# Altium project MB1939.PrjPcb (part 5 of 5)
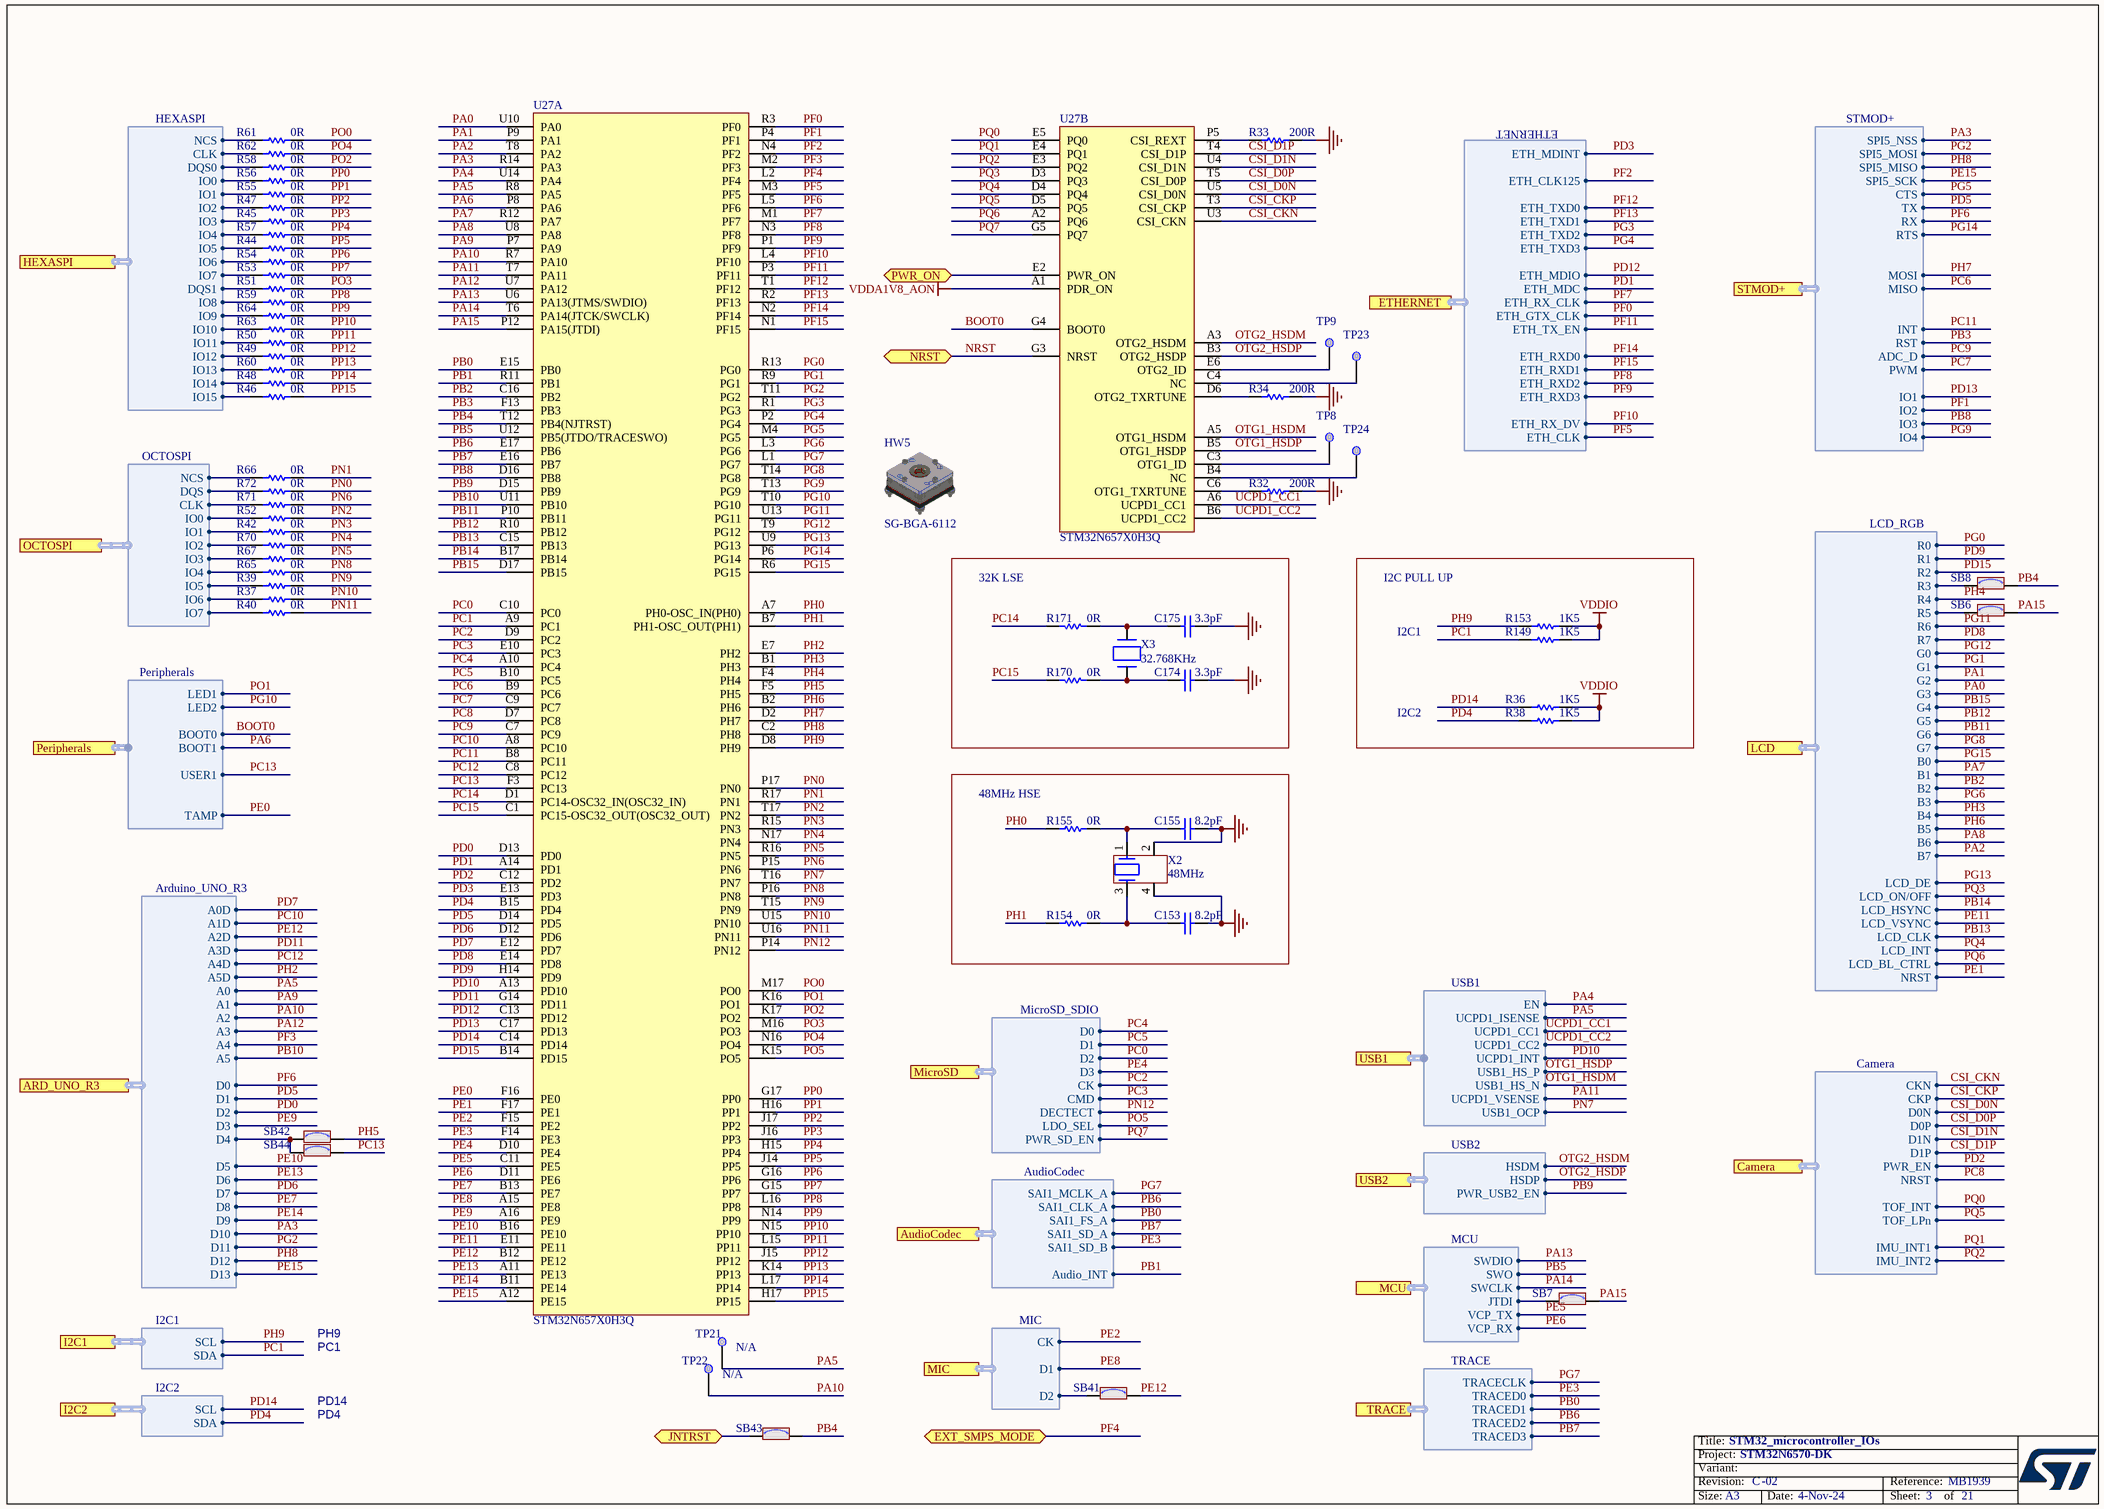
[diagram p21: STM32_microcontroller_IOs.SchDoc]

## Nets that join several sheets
5V: Arduino_UNO_R3_SMD (CN8.5), LCD (R43.1), STLINK_V3EC (D2.1 R113.2), STMOD+ (CN4.6 CN4.15), USB2 (C190.2 U47.5), USB1_DRP (SB48.1), Camera (C199.2 U54.3), Power (21 pins)
5V_STLK: STLINK_V3EC (6 pins), Power (JP2.1)
5V_USB_SNK: USB1_DRP (SB46.1), Power (JP2.3)
5V_VIN: Arduino_UNO_R3_SMD (R111.2), Power (C134.2 JP2.5 U21.2 U21.4)
GND: Arduino_UNO_R3_SMD (15 pins), Ethernet (38 pins), External_Debug_Interface (13 pins), HexaSPI_PSRAM (6 pins), LCD (13 pins), Peripherals (12 pins), MEMs_microphone (7 pins), OctoSPI_Flash (9 pins), SDcard (18 pins), STLINK_V3EC (105 pins), STMOD+ (CN4.5 CN4.16), USB2 (11 pins), Mechanical (H1.1 H2.1 H7.1 H8.1), STM32_microcontroller_power (76 pins), Audio_Codec (21 pins), USB1_DRP (26 pins), Camera (27 pins), Power (53 pins), STM32_microcontroller_IOs (9 pins)
VDD1V8: STM32_microcontroller_power (L4.1 L8.1), Power (R21.2)
VDD3V3: Arduino_UNO_R3_SMD (CN8.2 CN8.4 R131.2), Ethernet (SB3.1), LCD (C81.1 CN3.50), Peripherals (LD1.1 LD2.1), MEMs_microphone (SB19.1), SDcard (R145.1), USB2 (LD8.1), STM32_microcontroller_power (R159.1), Audio_Codec (SB38.1), USB1_DRP (LD10.1 R212.1 U46.2), Camera (SB45.1), Power (5 pins)
VDDA1V8: Arduino_UNO_R3_SMD (U6.8 U7.8 U8.8), HexaSPI_PSRAM (SB35.1), OctoSPI_Flash (SB36.1), SDcard (R143.2 U32.1), STM32_microcontroller_power (22 pins), Audio_Codec (SB37.1), Power (R179.2 TP17.1)
VDDA1V8_AON: STM32_microcontroller_power (C36.2 R148.1), Power (R163.2 TP15.1), STM32_microcontroller_IOs (U27.A1)
VDDCORE: STM32_microcontroller_power (21 pins), Power (R30.2 TP10.1)
VDDIO: External_Debug_Interface (CN1.1 CN10.1 R5.2), Peripherals (6 pins), SDcard (C152.2 U32.5), STLINK_V3EC (LNK3.1), STM32_microcontroller_power (17 pins), Power (R78.2 TP13.1), STM32_microcontroller_IOs (R36.1 R38.1 R149.1 R153.1)
VDDIO_SD: SDcard (6 pins), STM32_microcontroller_power (C59.2 C64.2 U27.E9 U27.F9)
VIN: Arduino_UNO_R3_SMD (CN8.8), Power (C131.2 U21.3)
VREFP: Arduino_UNO_R3_SMD (C140.1 R137.2), STM32_microcontroller_power (C38.2 C39.2 R27.2 U27.U2)
ARD_A0: Arduino_UNO_R3_SMD (SB49.2), USB1_DRP (SB47.1), STM32_microcontroller_IOs (TP21.1 U27.R8)
ARD_A0D: Arduino_UNO_R3_SMD (SB23.1), STM32_microcontroller_IOs (U27.E12)
ARD_A1: Arduino_UNO_R3_SMD (U8.6 U8.7), STM32_microcontroller_IOs (U27.P7)
ARD_A1D: Arduino_UNO_R3_SMD (SB22.1), STM32_microcontroller_IOs (U27.A8)
ARD_A2: Arduino_UNO_R3_SMD (SB51.2), STM32_microcontroller_IOs (TP22.1 U27.R7)
ARD_A2D: Arduino_UNO_R3_SMD (SB21.1), STM32_microcontroller_IOs (SB41.2 U27.B12)
ARD_A3: Arduino_UNO_R3_SMD (U7.6 U7.7), STM32_microcontroller_IOs (U27.U7)
ARD_A3D: Arduino_UNO_R3_SMD (SB20.1), STM32_microcontroller_IOs (U27.G14)
ARD_A4: Arduino_UNO_R3_SMD (TP5.1 U6.1 U6.2), STM32_microcontroller_IOs (U27.M2)
ARD_A4D: Arduino_UNO_R3_SMD (SB31.1), STM32_microcontroller_IOs (U27.C8)
ARD_A5: Arduino_UNO_R3_SMD (U6.6 U6.7), STM32_microcontroller_IOs (U27.U11)
ARD_A5D: Arduino_UNO_R3_SMD (SB33.1), STM32_microcontroller_IOs (U27.E7)
ARD_D0: Arduino_UNO_R3_SMD (CN11.1), STMOD+ (SB14.1), STM32_microcontroller_IOs (U27.L5)
ARD_D1: Arduino_UNO_R3_SMD (CN11.2), STMOD+ (SB12.1), STM32_microcontroller_IOs (U27.D14)
ARD_D2: Arduino_UNO_R3_SMD (CN11.3), STM32_microcontroller_IOs (U27.D13)
ARD_D3: Arduino_UNO_R3_SMD (CN11.4), STM32_microcontroller_IOs (U27.A16)
ARD_D4: Arduino_UNO_R3_SMD (CN11.5), STM32_microcontroller_IOs (SB42.1 SB44.1)
ARD_D5: Arduino_UNO_R3_SMD (CN11.6), STM32_microcontroller_IOs (U27.B16)
ARD_D6: Arduino_UNO_R3_SMD (CN11.7), STM32_microcontroller_IOs (U27.A11)
ARD_D7: Arduino_UNO_R3_SMD (CN11.8), STM32_microcontroller_IOs (U27.D12)
ARD_D8: Arduino_UNO_R3_SMD (CN12.1), STM32_microcontroller_IOs (U27.B13)
ARD_D9: Arduino_UNO_R3_SMD (CN12.2), STM32_microcontroller_IOs (U27.B11)
ARD_D10: Arduino_UNO_R3_SMD (CN12.3), STMOD+ (SB11.1), STM32_microcontroller_IOs (U27.R14)
ARD_D11: Arduino_UNO_R3_SMD (CN12.4), STMOD+ (SB13.1), STM32_microcontroller_IOs (U27.T11)
ARD_D12: Arduino_UNO_R3_SMD (CN12.5), STMOD+ (SB15.1), STM32_microcontroller_IOs (U27.C2)
ARD_D13: Arduino_UNO_R3_SMD (CN12.6 SB25.1), STMOD+ (SB18.1), STM32_microcontroller_IOs (U27.A12)
ARD_D14: Arduino_UNO_R3_SMD (CN12.9 SB32.1), STMOD+ (CN4.10), Camera (CN14.21 U41.1), STM32_microcontroller_IOs (R149.2 U27.A9)
ARD_D15: Arduino_UNO_R3_SMD (CN12.10 SB34.1), STMOD+ (CN4.7), Camera (CN14.20 U40.1), STM32_microcontroller_IOs (R153.2 U27.D8)
AUDIO_INT: Audio_Codec (R147.2), STM32_microcontroller_IOs (U27.R11)
BOOT0: Peripherals (R103.2), STM32_microcontroller_IOs (U27.G4)
BOOT1: Peripherals (R102.2), STM32_microcontroller_IOs (U27.P8)
CK: MEMs_microphone (CN5.4 R104.2), STM32_microcontroller_IOs (U27.F15)
CSI_CKN: Camera (U31.5), STM32_microcontroller_IOs (U27.U3)
CSI_CKP: Camera (U31.6), STM32_microcontroller_IOs (U27.T3)
CSI_D0_N: Camera (U29.5), STM32_microcontroller_IOs (U27.U5)
CSI_D0_P: Camera (U29.6), STM32_microcontroller_IOs (U27.T5)
CSI_D1_N: Camera (U30.5), STM32_microcontroller_IOs (U27.U4)
CSI_D1_P: Camera (U30.6), STM32_microcontroller_IOs (U27.T4)
D1: MEMs_microphone (TP18.1 U14.4), STM32_microcontroller_IOs (U27.A15)
D2: MEMs_microphone (CN5.5), STM32_microcontroller_IOs (SB41.1)
EN_MODULE: Camera (CN14.18 R222.2 U39.1), STM32_microcontroller_IOs (U27.C12)
ETH_CLK: Ethernet (R203.2), STM32_microcontroller_IOs (U27.M3)
ETH_CLK125: Ethernet (R196.1), STM32_microcontroller_IOs (U27.N4)
ETH_GTX_CLK: Ethernet (R160.1), STM32_microcontroller_IOs (U27.R3)
ETH_MDC: Ethernet (R204.1 U44.13), STM32_microcontroller_IOs (U27.A14)
ETH_MDINT: Ethernet (R186.1 U44.31), STM32_microcontroller_IOs (U27.E13)
ETH_MDIO: Ethernet (R200.1 U44.14), STM32_microcontroller_IOs (U27.C13)
ETH_RX_CLK: Ethernet (R13.2 R176.1 R180.1), STM32_microcontroller_IOs (U27.M1)
ETH_RX_DV: Ethernet (R14.2 R177.1 R181.1), STM32_microcontroller_IOs (U27.L4)
ETH_RXD0: Ethernet (R15.2 R174.1 R182.1), STM32_microcontroller_IOs (U27.N2)
ETH_RXD1: Ethernet (R16.2 R178.1 R183.1), STM32_microcontroller_IOs (U27.N1)
ETH_RXD2: Ethernet (R17.2 R184.1), STM32_microcontroller_IOs (U27.N3)
ETH_RXD3: Ethernet (R18.2 R175.1 R185.1), STM32_microcontroller_IOs (U27.P1)
ETH_TX_EN: Ethernet (R161.1), STM32_microcontroller_IOs (U27.P3)
ETH_TXD0: Ethernet (R162.1), STM32_microcontroller_IOs (U27.T1)
ETH_TXD1: Ethernet (R166.1), STM32_microcontroller_IOs (U27.R2)
ETH_TXD2: Ethernet (R169.1), STM32_microcontroller_IOs (U27.R1)
ETH_TXD3: Ethernet (R172.1), STM32_microcontroller_IOs (U27.P2)
HEXASPI_CLK: HexaSPI_PSRAM (U26.B2), STM32_microcontroller_IOs (R62.1)
HEXASPI_DQS0: HexaSPI_PSRAM (U26.C3), STM32_microcontroller_IOs (R58.1)
HEXASPI_DQS1: HexaSPI_PSRAM (U26.B3), STM32_microcontroller_IOs (R51.1)
HEXASPI_IO0: HexaSPI_PSRAM (U26.D3), STM32_microcontroller_IOs (R56.1)
HEXASPI_IO1: HexaSPI_PSRAM (U26.D2), STM32_microcontroller_IOs (R55.1)
HEXASPI_IO2: HexaSPI_PSRAM (U26.C4), STM32_microcontroller_IOs (R47.1)
HEXASPI_IO3: HexaSPI_PSRAM (U26.D4), STM32_microcontroller_IOs (R45.1)
HEXASPI_IO4: HexaSPI_PSRAM (U26.D5), STM32_microcontroller_IOs (R57.1)
HEXASPI_IO5: HexaSPI_PSRAM (U26.E3), STM32_microcontroller_IOs (R44.1)
HEXASPI_IO6: HexaSPI_PSRAM (U26.E2), STM32_microcontroller_IOs (R54.1)
HEXASPI_IO7: HexaSPI_PSRAM (U26.E1), STM32_microcontroller_IOs (R53.1)
HEXASPI_IO8: HexaSPI_PSRAM (U26.C2), STM32_microcontroller_IOs (R59.1)
HEXASPI_IO9: HexaSPI_PSRAM (U26.B1), STM32_microcontroller_IOs (R64.1)
HEXASPI_IO10: HexaSPI_PSRAM (U26.A2), STM32_microcontroller_IOs (R63.1)
HEXASPI_IO11: HexaSPI_PSRAM (U26.A4), STM32_microcontroller_IOs (R50.1)
HEXASPI_IO12: HexaSPI_PSRAM (U26.A5), STM32_microcontroller_IOs (R49.1)
HEXASPI_IO13: HexaSPI_PSRAM (U26.B4), STM32_microcontroller_IOs (R60.1)
HEXASPI_IO14: HexaSPI_PSRAM (U26.B5), STM32_microcontroller_IOs (R48.1)
HEXASPI_IO15: HexaSPI_PSRAM (U26.C5), STM32_microcontroller_IOs (R46.1)
HEXASPI_NCS: HexaSPI_PSRAM (R138.1 U26.A3), STM32_microcontroller_IOs (R61.1)
I2C2_SCL: LCD (R68.2), Audio_Codec (R226.2), USB1_DRP (R206.1), STM32_microcontroller_IOs (R36.2 U27.C14)
I2C2_SDA: LCD (R69.2), Audio_Codec (R227.2), USB1_DRP (R202.1), STM32_microcontroller_IOs (R38.2 U27.B15)
I_SENS_INT_VDDCORE_N: STM32_microcontroller_power (5 pins), Power (CN2.10)
I_SENS_INT_VDDCORE_P: STM32_microcontroller_power (8 pins), Power (CN2.9)
IMU_INT1: Camera (CN14.14 U36.1), STM32_microcontroller_IOs (U27.E4)
IMU_INT2: Camera (CN14.15 U37.1), STM32_microcontroller_IOs (U27.E3)
JNTRST: External_Debug_Interface (SB2.2 U23.4), STM32_microcontroller_IOs (SB43.1)
LCD_B0: LCD (CN3.21), STM32_microcontroller_IOs (U27.R6)
LCD_B1: LCD (CN3.23), STM32_microcontroller_IOs (U27.R12)
LCD_B2: LCD (CN3.25), STM32_microcontroller_IOs (U27.C16)
LCD_B3: LCD (CN3.27), STM32_microcontroller_IOs (U27.L3)
LCD_B4: LCD (CN3.29), STM32_microcontroller_IOs (U27.B1)
LCD_B5: LCD (CN3.31), STM32_microcontroller_IOs (U27.B2)
LCD_B6: LCD (CN3.33 TP1.1), STM32_microcontroller_IOs (U27.U8)
LCD_B7: LCD (CN3.35), STM32_microcontroller_IOs (U27.T8)
LCD_BL_CTRL: LCD (CN3.43), STM32_microcontroller_IOs (U27.A2)
LCD_CLK: LCD (CN3.32), STM32_microcontroller_IOs (U27.C15)
LCD_DE: LCD (CN3.22), STM32_microcontroller_IOs (U27.U9)
LCD_G0: LCD (CN3.4), STM32_microcontroller_IOs (U27.T9)
LCD_G1: LCD (CN3.6), STM32_microcontroller_IOs (U27.R9)
LCD_G2: LCD (CN3.8), STM32_microcontroller_IOs (U27.P9)
LCD_G3: LCD (CN3.10), STM32_microcontroller_IOs (U27.U10)
LCD_G4: LCD (CN3.12), STM32_microcontroller_IOs (U27.D17)
LCD_G5: LCD (CN3.14), STM32_microcontroller_IOs (U27.R10)
LCD_G6: LCD (CN3.16), STM32_microcontroller_IOs (U27.P10)
LCD_G7: LCD (CN3.18), STM32_microcontroller_IOs (U27.T14)
LCD_HSYNC: LCD (CN3.26), STM32_microcontroller_IOs (U27.B17)
LCD_INT: LCD (CN3.39), STM32_microcontroller_IOs (U27.D4)
LCD_NRST: LCD (CN3.36), STM32_microcontroller_IOs (U27.F17)
LCD_ON/OFF: LCD (SB5.2), STM32_microcontroller_IOs (U27.D3)
LCD_R0: LCD (CN3.3), STM32_microcontroller_IOs (U27.R13)
LCD_R1: LCD (CN3.5), STM32_microcontroller_IOs (U27.H14)
LCD_R2: LCD (CN3.7), STM32_microcontroller_IOs (U27.B14)
LCD_R3: LCD (CN3.9), STM32_microcontroller_IOs (SB8.1)
LCD_R4: LCD (CN3.11), STM32_microcontroller_IOs (U27.F4)
LCD_R5: LCD (CN3.13), STM32_microcontroller_IOs (SB6.1)
LCD_R6: LCD (CN3.15), STM32_microcontroller_IOs (U27.U13)
LCD_R7: LCD (CN3.17), STM32_microcontroller_IOs (U27.E14)
LCD_VSYNC: LCD (CN3.28), STM32_microcontroller_IOs (U27.E11)
LED1: Peripherals (R4.2), STM32_microcontroller_IOs (U27.K16)
LED2: Peripherals (R2.1), STM32_microcontroller_IOs (U27.T10)
MCU.JTDI: External_Debug_Interface (CN1.8 CN10.8 U24.4), STLINK_V3EC (R122.2), STM32_microcontroller_IOs (SB7.1)
MCU.SWCLK: External_Debug_Interface (CN1.4 CN10.4 U24.1), STLINK_V3EC (R95.2), STM32_microcontroller_IOs (U27.T6)
MCU.SWDIO: External_Debug_Interface (CN1.2 CN10.2 U24.5), STLINK_V3EC (R94.2), STM32_microcontroller_IOs (U27.U6)
MCU.SWO: External_Debug_Interface (CN1.6 CN10.6 U24.3), STLINK_V3EC (R116.2), STM32_microcontroller_IOs (U27.U12)
MCU.VCP_RX: External_Debug_Interface (U23.3), STLINK_V3EC (R114.2), STM32_microcontroller_IOs (U27.D11)
MCU.VCP_TX: External_Debug_Interface (U23.1), STLINK_V3EC (R112.2), STM32_microcontroller_IOs (U27.C11)
NRST: Arduino_UNO_R3_SMD (CN8.3), Ethernet (D7.2), External_Debug_Interface (CN1.10 CN10.10 U23.5), Peripherals (B1.1 B1.2 C198.2 U9.1), OctoSPI_Flash (D4.2), SDcard (D6.2), STLINK_V3EC (R117.2), STM32_microcontroller_IOs (U27.G3)
NRST_CAM: Camera (CN14.17 R221.2 U38.1), STM32_microcontroller_IOs (U27.D7)
OCTOSPI_CLK: OctoSPI_Flash (U25.B2), STM32_microcontroller_IOs (R71.1)
OCTOSPI_DQS: OctoSPI_Flash (U25.C3), STM32_microcontroller_IOs (R72.1)
OCTOSPI_IO0: OctoSPI_Flash (U25.D3), STM32_microcontroller_IOs (R52.1)
OCTOSPI_IO1: OctoSPI_Flash (U25.D2), STM32_microcontroller_IOs (R42.1)
OCTOSPI_IO2: OctoSPI_Flash (U25.C4), STM32_microcontroller_IOs (R70.1)
OCTOSPI_IO3: OctoSPI_Flash (U25.D4), STM32_microcontroller_IOs (R67.1)
OCTOSPI_IO4: OctoSPI_Flash (U25.D5), STM32_microcontroller_IOs (R65.1)
OCTOSPI_IO5: OctoSPI_Flash (U25.E3), STM32_microcontroller_IOs (R39.1)
OCTOSPI_IO6: OctoSPI_Flash (U25.E2), STM32_microcontroller_IOs (R37.1)
OCTOSPI_IO7: OctoSPI_Flash (U25.E1), STM32_microcontroller_IOs (R40.1)
OCTOSPI_NCS: OctoSPI_Flash (R141.1 R142.1), STM32_microcontroller_IOs (R66.1)
OTG1_HS_N: USB1_DRP (U51.5), STM32_microcontroller_IOs (U27.A5)
OTG1_HS_P: USB1_DRP (U51.6), STM32_microcontroller_IOs (U27.B5)
OTG2_HSD_N: USB2 (U49.5), STM32_microcontroller_IOs (U27.A3)
OTG2_HSD_P: USB2 (U49.6), STM32_microcontroller_IOs (U27.B3)
PA4: USB1_DRP (R210.2 U46.20), STM32_microcontroller_IOs (U27.U14)
PA11: USB1_DRP (C151.2 R151.2 R152.1), STM32_microcontroller_IOs (U27.T7)
PB0: External_Debug_Interface (SB26.2), Audio_Codec (SB57.2), STM32_microcontroller_IOs (U27.E15)
PB3: STMOD+ (CN4.12), STM32_microcontroller_IOs (U27.F13)
PB6: External_Debug_Interface (SB28.2), Audio_Codec (SB56.2), STM32_microcontroller_IOs (U27.E17)
PB7: External_Debug_Interface (SB27.2), Audio_Codec (SB58.2), STM32_microcontroller_IOs (U27.E16)
PB8: STMOD+ (CN4.19), STM32_microcontroller_IOs (U27.D16)
PB9: USB2 (R201.2 U47.4), STM32_microcontroller_IOs (U27.D15)
PC0: SDcard (CN13.1 R77.1 U4.5 U4.6), STM32_microcontroller_IOs (U27.C10)
PC2: SDcard (CN13.5 U4.1 U4.10), STM32_microcontroller_IOs (U27.D9)
PC3: SDcard (CN13.3 R75.1 U4.2 U4.9), STM32_microcontroller_IOs (U27.E10)
PC4: SDcard (CN13.7 R74.1 U3.2 U3.9), STM32_microcontroller_IOs (U27.A10)
PC5: SDcard (CN13.8 R73.1 U3.1 U3.10), STM32_microcontroller_IOs (U27.B10)
PC6: STMOD+ (CN4.9), STM32_microcontroller_IOs (U27.B9)
PC7: STMOD+ (CN4.14), STM32_microcontroller_IOs (U27.C9)
PC9: STMOD+ (SB16.2 TP3.1), STM32_microcontroller_IOs (U27.C7)
PC11: STMOD+ (CN4.11), STM32_microcontroller_IOs (U27.B8)
PC13: Peripherals (B2.3 B2.4 R225.2 U10.1), STM32_microcontroller_IOs (SB44.2 U27.F3)
PD10: USB1_DRP (U46.19), STM32_microcontroller_IOs (U27.A13)
PD13: STMOD+ (CN4.17), STM32_microcontroller_IOs (U27.C17)
PE0: Peripherals (B4.3 B4.4 R224.2 U12.1), STM32_microcontroller_IOs (U27.F16)
PE3: External_Debug_Interface (SB30.2), Audio_Codec (SB59.2), STM32_microcontroller_IOs (U27.F14)
PE4: SDcard (CN13.2 R76.1 U4.4 U4.7), STM32_microcontroller_IOs (U27.D10)
PF1: STMOD+ (CN4.18), STM32_microcontroller_IOs (U27.P4)
PF4: Power (R158.1 R223.2), STM32_microcontroller_IOs (U27.L2)
PG5: STMOD+ (SB10.1), STM32_microcontroller_IOs (U27.M4)
PG7: External_Debug_Interface (SB29.2), Audio_Codec (SB55.2), STM32_microcontroller_IOs (U27.L1)
PG9: STMOD+ (CN4.20), STM32_microcontroller_IOs (U27.T13)
PG14: STMOD+ (SB17.1), STM32_microcontroller_IOs (U27.P6)
PH7: STMOD+ (CN4.8), STM32_microcontroller_IOs (U27.D2)
PN7: USB1_DRP (R216.2), STM32_microcontroller_IOs (U27.T16)
PN12: SDcard (CN13.10 R143.1), STM32_microcontroller_IOs (U27.P14)
PO5: SDcard (R150.2 U32.6), STM32_microcontroller_IOs (U27.K15)
PQ0: Camera (CN14.12 U35.1), STM32_microcontroller_IOs (U27.E5)
PQ5: Camera (CN14.11 U33.1), STM32_microcontroller_IOs (U27.D5)
PQ7: SDcard (D5.2), STM32_microcontroller_IOs (U27.G5)
PWR_ON: SDcard (R144.1), Power (5 pins), STM32_microcontroller_IOs (U27.E2)
STMOD_ADC: Arduino_UNO_R3_SMD (SB9.2), STMOD+ (CN4.13 SB16.1)
UCPD1_CC1: USB1_DRP (U46.1), STM32_microcontroller_IOs (U27.A6)
UCPD1_CC2: USB1_DRP (U46.3), STM32_microcontroller_IOs (U27.B6)

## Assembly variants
N6570_S: not fitted C123 C125 C138 C196 CN1 CN9 R5 R12 R15 R16 R18 R21 R22 R118 R120 R137 R173 R176 R177 R203 R209 SB32 SB34 SB47 U18 U27
N6570: not fitted C15 C123 C125 C138 C156 C196 CN1 CN9 HW5 R5 R12 R15 R16 R18 R21 R22 R118 R120 R137 R173 R176 R177 R203 R209 R221 R222 R224 R225 SB11 SB13 SB15 SB18 SB32 SB34 SB40 SB41 SB44 SB47 SB53 SB54 U18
